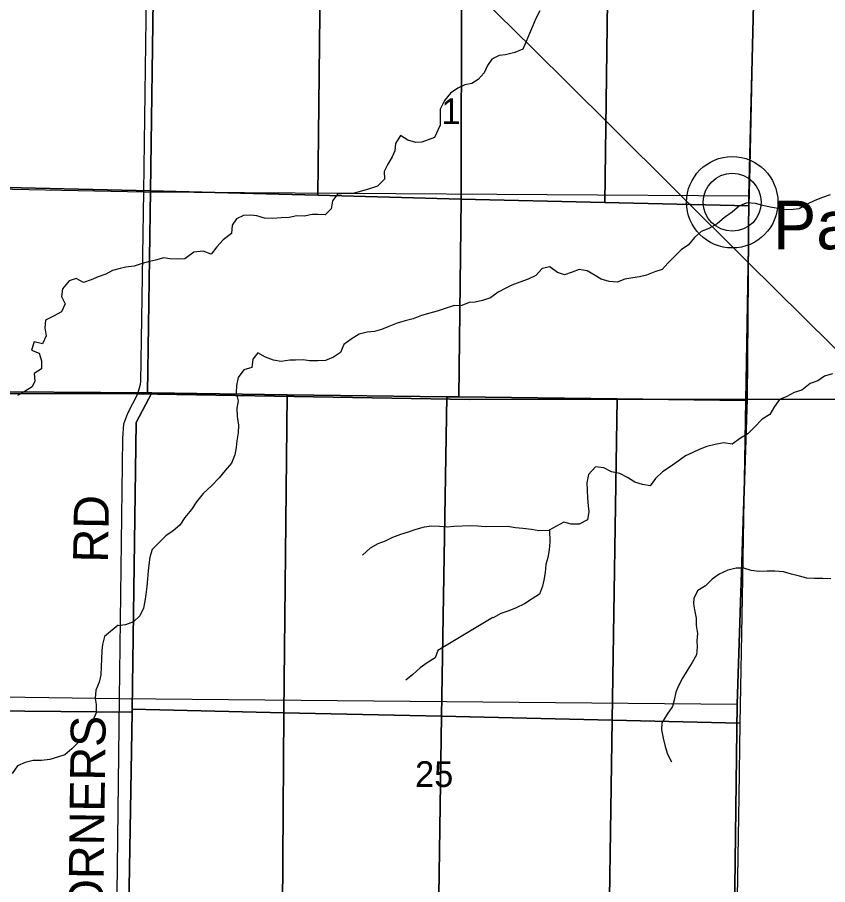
# Model space of a CAD drawing. Extents: x 1985906 to 2277390, y 930619 to 1324581.
# Drawn here: x 2079054 to 2086022, y 1111832 to 1119287 of the extents above; entities that cross this region are included whole.
import ezdxf

# ---------------------------------------------------------------- set-up
doc = ezdxf.new("R2010")
doc.units = 0
for name, color, linetype in [('GM_X_County_Road', 7, 'Continuous'), ('GM_X_Minor_River', 7, 'Continuous'), ('GM_X_Rail_Line', 7, 'Continuous'), ('GM_X_Section', 7, 'Continuous'), ('GM_X_Section_Text', 7, 'Continuous'), ('GM_X_Township', 7, 'Continuous'), ('GM_X_Township_Road', 7, 'Continuous'), ('GM_X_Township_Road_Text', 7, 'Continuous'), ('GM_X_Unincorporated', 7, 'Continuous'), ('GM_X_Unincorporated_Location', 7, 'Continuous'), ('GM_X_Unincorporated_Text', 7, 'Continuous')]:
    doc.layers.add(name, color=color, linetype=linetype)

msp = doc.modelspace()

# ---------------------------------------------------------------- linework, layer by layer
at = {"layer": 'GM_X_County_Road'}
for points in [[(2085328.7, 1116004.2), (2085345.3, 1117751.5), (2085400.5, 1120106.1), (2085479.8, 1124404.8)], [(2072237.1, 1117947.9), (2080142.8, 1117786.3), (2085345.3, 1117751.5)], [(2085073.8, 1102568.7), (2085080.1, 1102788.8), (2085158.3, 1108209.7), (2085192.3, 1109330.7), (2085243.4, 1113383.3), (2085328.7, 1116004.2)], [(2071769.5, 1113528.2), (2074247.6, 1113511.8), (2079934.2, 1113433.1), (2085243.4, 1113383.3)]]:
    msp.add_lwpolyline(points, dxfattribs=at)
at = {"layer": 'GM_X_Minor_River'}
for points in [[(2083547.9, 1119342), (2083512.4, 1119275.5), (2083484.8, 1119209.1), (2083457.3, 1119146.7), (2083429.8, 1119078.2), (2083400.3, 1119011.8), (2083332.2, 1118985.2), (2083252.1, 1118964.5), (2083198, 1118960), (2083134, 1118927.4), (2083096.4, 1118873), (2083068.8, 1118808.5), (2083017.2, 1118751.9), (2082963.2, 1118719.4), (2082903.1, 1118706.9), (2082841.2, 1118678.3), (2082779.3, 1118633.7), (2082727.7, 1118573.1), (2082690.2, 1118496.6), (2082688.8, 1118428.3), (2082691.4, 1118360.1), (2082640, 1118254.6)], [(2082640, 1118253), (2082532.1, 1118212.4), (2082482, 1118210), (2082413.5, 1118231.6), (2082348.9, 1118271.2), (2082307.4, 1118202.7), (2082299.9, 1118138.4), (2082278.3, 1118088.1), (2082240.7, 1118025.6), (2082209.1, 1117963.1), (2082211.7, 1117894.9), (2082150.1, 1117834.2), (2082082, 1117811.6), (2082013.9, 1117793), (2081949.8, 1117776.5), (2081879.6, 1117773.9), (2081807.4, 1117767.4), (2081763.8, 1117708.8), (2081752.3, 1117640.5), (2081700.6, 1117590), (2081638.3, 1117591.5), (2081588.1, 1117593.1), (2081520, 1117576.5), (2081457.8, 1117580.1), (2081391.7, 1117567.5), (2081323.5, 1117563), (2081251.3, 1117556.4), (2081181, 1117559.9), (2081114.6, 1117579.4), (2081062.3, 1117585), (2081000.1, 1117582.5), (2080938.1, 1117556), (2080900.5, 1117501.5), (2080897.1, 1117429.2), (2080823.3, 1117374.5), (2080769.6, 1117313.9), (2080720, 1117251.3), (2080651.5, 1117276.9), (2080571.3, 1117268.2), (2080495.5, 1117211.4), (2080431.3, 1117208.9), (2080365.1, 1117212.4), (2080314.8, 1117220.1), (2080242.7, 1117199.4), (2080190.7, 1117187), (2080126.6, 1117170.5), (2080058.5, 1117147.9), (2079988.3, 1117139.3), (2079938.3, 1117128.9), (2079872.2, 1117110.3), (2079816.3, 1117077.8), (2079748.2, 1117057.2), (2079688.2, 1117030.6), (2079624.2, 1117008.1), (2079559.7, 1117041.7), (2079499.6, 1117023.2), (2079444, 1116954.5), (2079434.5, 1116888.2), (2079465.2, 1116824.2), (2079433.7, 1116755.8), (2079365.8, 1116719.1), (2079297.8, 1116682.5), (2079290.4, 1116618.2), (2079301, 1116548.1), (2079271.5, 1116479.7), (2079199.1, 1116497.2), (2079175.6, 1116426.8), (2079242.1, 1116399.2), (2079260.8, 1116333.1), (2079263.4, 1116264.9), (2079199.5, 1116224.3), (2079206.1, 1116160.1), (2079182.4, 1116109.8), (2079120.5, 1116073.2), (2079054.6, 1116036.6)], [(2086042.7, 1117760), (2085978.7, 1117739.4), (2085912.7, 1117712.8), (2085846.7, 1117680.2), (2085776.8, 1117641.6), (2085726.7, 1117635.1), (2085658.5, 1117632.6), (2085596.2, 1117642.2), (2085527.8, 1117653.7), (2085465.4, 1117669.2), (2085401.1, 1117686.8), (2085330.8, 1117692.3), (2085264.8, 1117665.7), (2085201, 1117613), (2085135.2, 1117566.4), (2085071.4, 1117511.7), (2085001.5, 1117471), (2084933.5, 1117446.4), (2084875.7, 1117393.8), (2084826.1, 1117331.2), (2084762.2, 1117288.6), (2084650.8, 1117175.3), (2084599.1, 1117118.8), (2084537.1, 1117100.2), (2084465.1, 1117071.6), (2084403, 1117055), (2084346.8, 1117048.6), (2084276.7, 1117036), (2084210.7, 1117011.4), (2084142.4, 1117016.9), (2084074, 1117036.4), (2084023.5, 1117068.1), (2083954.9, 1117107.8), (2083884.6, 1117119.2), (2083824.5, 1117096.7), (2083758.5, 1117074.1), (2083698.1, 1117093.7), (2083633.4, 1117143.4), (2083567.4, 1117126.8), (2083513.7, 1117068.2)], [(2083513.7, 1117068.2), (2083447.7, 1117037.6), (2083375.7, 1117011), (2083307.7, 1116984.4), (2083255.7, 1116957.9), (2083189.8, 1116925.3), (2083121.9, 1116876.6), (2083053.9, 1116854), (2082989.8, 1116839.4), (2082939.6, 1116835), (2082875.6, 1116810.5), (2082809.4, 1116807.9)], [(2082811.1, 1116809.8), (2082663.3, 1116760.7), (2082601.2, 1116744.1), (2082529.1, 1116723.5), (2082459.1, 1116694.9), (2082389, 1116678.3), (2082319, 1116657.7), (2082249, 1116629.1), (2082184.9, 1116604.5), (2082124.9, 1116585.9), (2082062.7, 1116579.5), (2081994.6, 1116562.9), (2081924.7, 1116520.2), (2081862.9, 1116473.6), (2081833.4, 1116407.1), (2081773.6, 1116364.5), (2081703.5, 1116337.9), (2081639.4, 1116333.4), (2081567.1, 1116334.8), (2081512.8, 1116342.5), (2081446.6, 1116339.9), (2081396.4, 1116339.6), (2081324.2, 1116329), (2081257.9, 1116340.5), (2081189.4, 1116366.1), (2081120.9, 1116401.6), (2081079.2, 1116349.1), (2081069.8, 1116276.8), (2081001.7, 1116256.2), (2080952.1, 1116189.6), (2080938.7, 1116123.3), (2080935.2, 1116059.1), (2080951.9, 1115991), (2080940.4, 1115926.7), (2080945, 1115854.5), (2080955.7, 1115782.4), (2080952.3, 1115714.1), (2080942.9, 1115645.8), (2080937.3, 1115589.6), (2080923.8, 1115527.3), (2080896.4, 1115454.9), (2080840.7, 1115390.2), (2080791.1, 1115327.6), (2080723.5, 1115258.9), (2080651.8, 1115194.1), (2080594.2, 1115123.5), (2080552.6, 1115054.9), (2080495, 1114988.3), (2080451.4, 1114921.7), (2080395.6, 1114873.1), (2080331.8, 1114830.5), (2080270.1, 1114769.8), (2080212.4, 1114711.2), (2080192.9, 1114646.8), (2080185.4, 1114580.6), (2080177.9, 1114530.4), (2080172.5, 1114460.1), (2080167, 1114393.8), (2080159.6, 1114325.6), (2080152, 1114269.3), (2080138.6, 1114207), (2080107, 1114142.6), (2080053.3, 1114090), (2079985.2, 1114065.4), (2079917.1, 1114056.8)], [(2086064.3, 1116223.1), (2085996.2, 1116202.5), (2085936.3, 1116161.9), (2085870.3, 1116139.3), (2085800.5, 1116082.6), (2085734.5, 1116062), (2085670.6, 1116027.4), (2085606.6, 1116000.8), (2085564.9, 1115940.3), (2085525.4, 1115871.8), (2085459.5, 1115833.1), (2085393.9, 1115764.4), (2085334.2, 1115705.7), (2085272.3, 1115669.1), (2085200.4, 1115618.4), (2085128.1, 1115629.9), (2085055.9, 1115615.3), (2084983.9, 1115596.7), (2084915.8, 1115572.1), (2084863.8, 1115547.6), (2084799.9, 1115517), (2084736.1, 1115470.4), (2084668.2, 1115421.7), (2084602.4, 1115381.1), (2084542.7, 1115322.4), (2084495, 1115259.8), (2084428.7, 1115271.4), (2084364.3, 1115290.9), (2084301.7, 1115332.6), (2084235.2, 1115366.2), (2084162.8, 1115379.7), (2084098.3, 1115413.3), (2084025.9, 1115422.8), (2083966.3, 1115356.1), (2083950.8, 1115285.7), (2083955.4, 1115221.6), (2083958, 1115153.4), (2083962.6, 1115089.2), (2083969.1, 1115039.1), (2083957.6, 1114968.8), (2083885.7, 1114930.1), (2083817.5, 1114931.6), (2083753.1, 1114947.1), (2083627.7, 1114877.7)], [(2083624.6, 1114874.7), (2083539, 1114873.2), (2083474.6, 1114884.8), (2083402.3, 1114892.2), (2083338, 1114897.8), (2083267.7, 1114909.3), (2083077, 1114907.8), (2083012.7, 1114913.3), (2082948.5, 1114914.8), (2082808, 1114909.8), (2082751.9, 1114903.3), (2082685.6, 1114908.8), (2082619.3, 1114914.3), (2082551.1, 1114903.8), (2082481.1, 1114885.2), (2082415, 1114862.6), (2082349, 1114842), (2082280.9, 1114815.4), (2082217, 1114784.8), (2082153, 1114760.2), (2082089.1, 1114723.6), (2082023.4, 1114662.9)], [(2083630.7, 1114877.7), (2083632.1, 1114779.6), (2083626.7, 1114709.4), (2083617.3, 1114643.1), (2083597.7, 1114582.7), (2083594.3, 1114514.5), (2083582.8, 1114450.2), (2083569.2, 1114397.9), (2083543.8, 1114329.5), (2083481.9, 1114288.9), (2083414, 1114246.2), (2083344.1, 1114211.6), (2083280.1, 1114185), (2083212, 1114162.4), (2083146.1, 1114123.8)], [(2086049.7, 1114459.1), (2085981.4, 1114462.6), (2085909.1, 1114464), (2085842.9, 1114465.5), (2085778.5, 1114483.1), (2085710.1, 1114500.6), (2085641.6, 1114520.2), (2085567.3, 1114527.6), (2085503.1, 1114527.1), (2085432.9, 1114522.6), (2085364.5, 1114532.1), (2085302.2, 1114551.7), (2085235.9, 1114551.2), (2085163.8, 1114534.6), (2085089.8, 1114499.9), (2085030, 1114457.3), (2084972.3, 1114400.7), (2084906.4, 1114360), (2084870.8, 1114295.5), (2084869.3, 1114245.3), (2084875.7, 1114195.2), (2084890.4, 1114123.1), (2084891, 1114058.9), (2084903.6, 1113990.8), (2084898.2, 1113926.5), (2084898.6, 1113876.3), (2084893.2, 1113808.1), (2084857.6, 1113741.6), (2084814.1, 1113673), (2084772.5, 1113606.5), (2084737, 1113536), (2084715.4, 1113485.7), (2084701.9, 1113417.3), (2084688.3, 1113363.1)], [(2083144.1, 1114128.3), (2082668.9, 1113843.2), (2082647.3, 1113780.8), (2082579.5, 1113738.2), (2082517.6, 1113695.6), (2082455.9, 1113638.9), (2082394.1, 1113590.3)], [(2079922.1, 1114063.1), (2079803.4, 1113965.7), (2079786, 1113897.3), (2079780.4, 1113845.1), (2079779.1, 1113772.8), (2079775.6, 1113704.6), (2079772.2, 1113634.3), (2079758.7, 1113572), (2079729.2, 1113503.6), (2079723.8, 1113431.3), (2079732.3, 1113381.2), (2079732.9, 1113309), (2079703.4, 1113242.5), (2079673.9, 1113178.1), (2079640.3, 1113117.6), (2079584.6, 1113061), (2079522.9, 1112998.4), (2079463.1, 1112947.7), (2079399.1, 1112927.2), (2079333, 1112908.6), (2079260.8, 1112898), (2079190.6, 1112899.5), (2079122.5, 1112880.9), (2079054.5, 1112854.3), (2079010.9, 1112787.8)], [(2084688.3, 1113363.1), (2084640.8, 1113296.5), (2084597.2, 1113223.9), (2084593.7, 1113163.7), (2084608.4, 1113091.5), (2084625.1, 1113019.4), (2084643.8, 1112953.3), (2084678.5, 1112887.4)]]:
    msp.add_lwpolyline(points, dxfattribs=at)
at = {"layer": 'GM_X_Rail_Line'}
msp.add_lwpolyline([(2083032.6, 1119468.7), (2083484.7, 1119022.1), (2084139.6, 1118372), (2085330.6, 1117189.3), (2087283.9, 1115255.6), (2087947.2, 1114597.1), (2088364.7, 1114183.2), (2088991.5, 1113563.9), (2089838.8, 1112724.1), (2090474, 1112095.4), (2091515.6, 1111062.2), (2092837.4, 1109753.5), (2093114, 1109478.8)], dxfattribs=at)
at = {"layer": 'GM_X_Section'}
for points in [[(2081678.8, 1121399.2), (2081637, 1117758.2), (2080198.4, 1117796.6), (2080225.6, 1119644.2), (2080251.5, 1121406.6)], [(2082875.3, 1121393.1), (2082870.4, 1117725.2), (2081637, 1117758.2), (2081678.8, 1121399.2)], [(2084155.8, 1121386.4), (2084106.9, 1117696.1), (2082870.4, 1117725.2), (2082875.3, 1121393.1)], [(2085424.2, 1121379.9), (2085412.4, 1120817.1), (2085381, 1119343.8), (2085351.9, 1118000.5), (2085344.9, 1117666.8), (2084106.9, 1117696.1), (2084155.8, 1121386.4)], [(2080225.6, 1119644.2), (2080198.4, 1117796.6), (2077598.4, 1117854.4), (2077509.7, 1117856.7), (2077549.7, 1119692.5)], [(2080198.4, 1117796.6), (2080172.8, 1116058.6), (2078558, 1116071.1), (2077529.9, 1116078.8), (2077598.4, 1117854.4)], [(2081637, 1117758.2), (2082870.4, 1117725.2), (2082851.1, 1116024.4), (2082747.5, 1116025.7), (2081375.4, 1116043.3), (2080211.9, 1116058.1), (2080172.8, 1116058.6), (2080198.4, 1117796.6)], [(2084106.9, 1117696.1), (2085344.9, 1117666.8), (2085335.5, 1117148), (2085314.5, 1115992.9), (2084210.8, 1116007), (2082851.1, 1116024.4), (2082870.4, 1117725.2)], [(2078558, 1116071.1), (2080172.8, 1116058.6), (2080211.9, 1116058.1), (2080075.1, 1115804.6), (2080041.4, 1113339.6), (2080041, 1113314.7), (2078502.3, 1113328.9)], [(2080211.9, 1116058.1), (2081375.4, 1116043.3), (2081345.5, 1113309.6), (2080041.4, 1113339.6), (2080075.1, 1115804.6)], [(2081375.4, 1116043.3), (2082747.5, 1116025.7), (2082700.8, 1113278.5), (2081345.5, 1113309.6)], [(2082747.5, 1116025.7), (2082851.1, 1116024.4), (2084210.8, 1116007), (2084167.9, 1113244.9), (2082700.8, 1113278.5)], [(2084210.8, 1116007), (2085314.5, 1115992.9), (2085286, 1114298.3), (2085267.8, 1113219.7), (2084167.9, 1113244.9)], [(2078502.3, 1113328.9), (2080041, 1113314.7), (2079999.7, 1110802), (2078451.4, 1110814.6)], [(2080041.4, 1113339.6), (2081345.5, 1113309.6), (2081329.3, 1110787.9), (2079999.7, 1110802), (2080041, 1113314.7)], [(2082700.8, 1113278.5), (2082665.3, 1110773.6), (2081329.3, 1110787.9), (2081345.5, 1113309.6)], [(2084167.9, 1113244.9), (2084131.3, 1110758.1), (2082692.1, 1110773.4), (2082665.3, 1110773.6), (2082700.8, 1113278.5)], [(2085267.8, 1113219.7), (2085257.3, 1112589.7), (2085236.4, 1111199.8), (2085229.6, 1110746.4), (2084131.3, 1110758.1), (2084167.9, 1113244.9)]]:
    msp.add_lwpolyline(points, close=True, dxfattribs=at)
at = {"layer": 'GM_X_Township'}
msp.add_lwpolyline([(2059091.9, 1116133.9), (2059120.2, 1118390.4), (2059186.4, 1123686.3), (2059259.3, 1129509), (2059329.7, 1135138.9), (2059427, 1142930.1), (2061929.5, 1142920.5), (2072418.8, 1142880.3), (2081417, 1142845.8), (2085793.3, 1142829), (2085729, 1138806.8), (2085675, 1134358), (2085604.1, 1129650), (2085479.7, 1124404.8), (2085400.5, 1120106.1), (2085345.3, 1117751.5), (2085328.7, 1116004.2), (2082946.6, 1116001.5), (2080089.5, 1116050.8), (2071945.4, 1116056.8), (2066831.4, 1116082.5), (2063355.9, 1116100), (2061552.3, 1116120.3)], close=True, dxfattribs=at)
for points in [[(2112984.3, 1116083.4), (2104968.7, 1116054), (2100204.9, 1116003.6), (2099440, 1115999.3), (2095790.6, 1115975.2), (2091530.9, 1115990.8), (2085328.7, 1116004.2), (2085345.3, 1117751.5), (2085400.5, 1120106.1), (2085479.7, 1124404.8), (2085604.1, 1129650), (2085675, 1134358), (2085729, 1138806.8), (2085793.3, 1142829), (2091370.5, 1142781.6), (2094059.5, 1142739.9), (2099759.2, 1142764.8), (2105186.3, 1142764.6), (2105809.5, 1142741.5), (2113092.4, 1142777.3)], [(2066831.4, 1116082.5), (2071945.4, 1116056.8), (2080089.5, 1116050.8), (2082946.6, 1116001.5), (2085328.7, 1116004.2), (2085243.4, 1113383.3), (2085192.2, 1109330.7), (2085158.3, 1108209.7), (2085080.2, 1102788.8), (2085073.8, 1102568.7), (2085023.9, 1098473.4)], [(2096607.4, 1089692.6), (2091363.3, 1089785.7), (2084867.6, 1089884.3), (2084882.5, 1090809.6), (2084914.3, 1093446.7), (2084916.2, 1093654.1), (2085024.3, 1098265.8), (2085023.9, 1098473.4), (2085073.8, 1102568.7), (2085080.2, 1102788.8), (2085158.3, 1108209.7), (2085192.2, 1109330.7), (2085243.4, 1113383.3), (2085328.7, 1116004.2), (2091530.9, 1115990.8), (2095790.6, 1115975.2)]]:
    msp.add_lwpolyline(points, dxfattribs=at)
at = {"layer": 'GM_X_Township_Road'}
for points in [[(2080142.8, 1117786.3), (2080142.8, 1117786.3), (2080183.7, 1120970.4), (2080183.7, 1120970.6)], [(2080114.2, 1116136.1), (2080116.8, 1116154.3), (2080142.8, 1117786.3)], [(2079915.4, 1111984.6), (2079915.4, 1111984.7), (2079934.2, 1113433.1), (2079962, 1115666.6), (2079969.6, 1115792.9), (2080005.4, 1115885.3), (2080089.5, 1116050.8), (2080113.9, 1116134), (2080114.2, 1116136.1)], [(2085328.7, 1116004.2), (2091530.9, 1115990.8)], [(2079867.2, 1108259.6), (2079915.4, 1111984.6)]]:
    msp.add_lwpolyline(points, dxfattribs=at)
at = {"layer": 'GM_X_Unincorporated'}
for radius in [392.8, 249]:
    msp.add_circle((2085201.5, 1117697.4), radius, dxfattribs=at)
at = {"layer": 'GM_X_Unincorporated_Location'}
msp.add_line((2085201.5, 1117697.4), (2085201.5, 1117697.4), dxfattribs=at)

# ---------------------------------------------------------------- texts
at = {"layer": 'GM_X_Section_Text'}
for s, p in [('1', (2082701, 1118369.5)), ('25', (2082474.4, 1112671.5))]:
    msp.add_text(s, height=221, rotation=0.00001, dxfattribs=at).set_placement(p)
at = {"layer": 'GM_X_Township_Road_Text'}
for s, rotation, p in [('RD', 89.01278, (2079833.1, 1114598.2)), ('CORNERS', 89.27305, (2079789, 1111275.6))]:
    msp.add_text(s, height=300, rotation=rotation, dxfattribs=at).set_placement(p)
at = {"layer": 'GM_X_Unincorporated_Text'}
msp.add_text('Pawnee', height=417, rotation=0.00001, dxfattribs=at).set_placement((2085552.2, 1117293.1))

doc.saveas('drawing.dxf')
